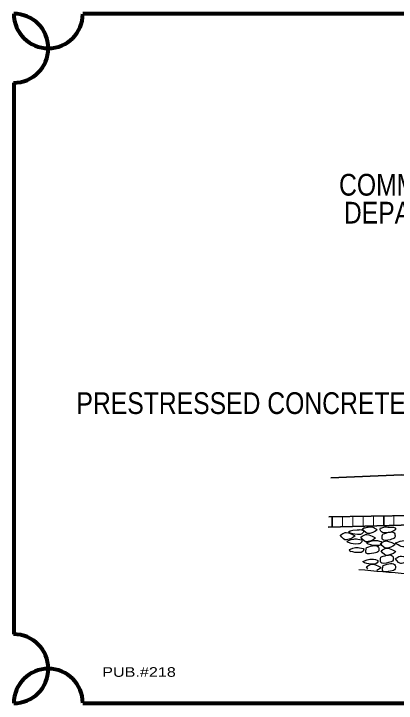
# Model space of a CAD drawing. Extents: x 763.8 to 797.8, y -170.3 to -127.3.
# Drawn here: x 764.76 to 775.84, y -147.27 to -127.27 of the extents above; entities that cross this region are included whole.
import ezdxf
from ezdxf.enums import TextEntityAlignment as Align

# ---------------------------------------------------------------- set-up
doc = ezdxf.new("R2010")
doc.units = 0
doc.header["$LTSCALE"] = 0.077
doc.layers.add('1', color=7, linetype='Continuous', lineweight=35)
doc.layers.add('63', color=7, linetype='Continuous', lineweight=13)

msp = doc.modelspace()

# ---------------------------------------------------------------- linework, layer by layer
at = {"layer": '1', "lineweight": 80}
for p, q in [((794.76075, -127.26542), (766.76075, -127.26542)), ((764.76075, -129.26542), (764.76075, -145.26542)), ((766.76075, -147.26542), (794.76075, -147.26542))]:
    msp.add_line(p, q, dxfattribs=at)
for centre, start, end in [((764.76073, -128.26542), 270, 90), ((765.76073, -127.26542), 180, 0), ((764.76073, -146.26542), 270, 90), ((765.76073, -147.26542), 0, 180)]:
    msp.add_arc(centre, 1, start, end, dxfattribs=at)
at = {"layer": '63', "lineweight": 35}
for p, q in [((773.89242, -141.85708), (776.85492, -141.81692)), ((773.98767, -141.85575), (773.98767, -142.1575)), ((775.48767, -141.83542), (775.48767, -142.112)), ((773.86917, -142.16108), (776.56758, -142.07925))]:
    msp.add_line(p, q, dxfattribs=at)
at = {"layer": '63'}
for p, q in [((774.28767, -141.85167), (774.28767, -142.14842)), ((774.58767, -141.84767), (774.58767, -142.13925)), ((774.88767, -141.84358), (774.88767, -142.13017)), ((775.18767, -141.8395), (775.18767, -142.12108)), ((775.77567, -141.8315), (775.77567, -142.10325))]:
    msp.add_line(p, q, dxfattribs=at)
at = {"layer": '63', "lineweight": 25}
msp.add_line((775.02017, -143.36542), (774.979, -143.31008), dxfattribs=at)
at = {"layer": '63', "lineweight": 35}
msp.add_lwpolyline([(773.95008, -140.723), (776.00742, -140.6415), (776.92408, -140.65583)], dxfattribs=at)
at = {"layer": '63', "lineweight": 25}
for points in [[(775.19208, -142.17617), (775.19975, -142.17883), (775.27542, -142.2165), (775.28433, -142.23358), (775.27275, -142.25175), (775.22142, -142.2865), (775.16758, -142.31133), (775.08317, -142.339), (775.04742, -142.34583), (775.021, -142.34617), (774.99975, -142.33983), (774.96142, -142.31675), (774.907, -142.26458), (774.86592, -142.20925)], [(774.87075, -142.20567), (774.90983, -142.179), (774.92233, -142.17142)], [(775.827, -142.18742), (775.82808, -142.20225), (775.82208, -142.224), (775.80567, -142.24308), (775.77725, -142.2625), (775.727, -142.28892), (775.66992, -142.31092), (775.645, -142.31725), (775.59483, -142.323), (775.55475, -142.32333), (775.49625, -142.3185), (775.447, -142.3085), (775.41967, -142.29508), (775.40125, -142.277), (775.38267, -142.23733), (775.38142, -142.20592), (775.38825, -142.18442), (775.39167, -142.17975)], [(774.22742, -142.38717), (774.2665, -142.3605), (774.29825, -142.34133), (774.32283, -142.32908), (774.36017, -142.31667), (774.37875, -142.31408), (774.39708, -142.3145), (774.45833, -142.32675), (774.55642, -142.36033), (774.63217, -142.39808), (774.641, -142.41517), (774.6295, -142.43333), (774.57808, -142.46808), (774.52425, -142.49283), (774.43983, -142.52058), (774.40408, -142.52742), (774.37767, -142.52775), (774.3565, -142.52142), (774.31817, -142.49833), (774.26367, -142.44617), (774.22258, -142.39083)], [(774.78142, -142.22808), (774.83767, -142.23833), (774.885, -142.25117), (774.90183, -142.26183), (774.907, -142.27525), (774.89867, -142.30408), (774.8815, -142.32675), (774.84517, -142.35608), (774.82492, -142.36592), (774.805, -142.37117), (774.72083, -142.37242), (774.64408, -142.36433), (774.58658, -142.35333), (774.51258, -142.32917), (774.48567, -142.31367), (774.46817, -142.296)], [(774.46817, -142.29117), (774.51325, -142.26958), (774.58883, -142.24458)], [(774.58325, -142.24708), (774.7105, -142.23442), (774.76775, -142.23442)], [(774.82225, -142.4455), (774.86142, -142.41892), (774.89308, -142.39975), (774.91767, -142.3875), (774.955, -142.375), (774.97358, -142.37242), (774.99192, -142.37283), (775.05325, -142.38517), (775.15125, -142.41875), (775.227, -142.45642), (775.23592, -142.4735), (775.22433, -142.49167), (775.173, -142.52642), (775.11908, -142.55117), (775.03467, -142.57892), (774.999, -142.58575), (774.97258, -142.58608), (774.95133, -142.57975), (774.913, -142.55667), (774.85858, -142.5045), (774.81742, -142.44917)], [(774.4185, -142.56667), (774.46367, -142.54508), (774.53917, -142.52), (774.61725, -142.50242), (774.64283, -142.49925), (774.69275, -142.4995), (774.73175, -142.5035), (774.78808, -142.51383), (774.83542, -142.52667), (774.85225, -142.53733), (774.85733, -142.55075), (774.84908, -142.5795), (774.83183, -142.60225), (774.7955, -142.6315), (774.77533, -142.64142), (774.75542, -142.64667), (774.67125, -142.64792), (774.59442, -142.63983), (774.537, -142.62883), (774.463, -142.60467), (774.436, -142.58917), (774.4185, -142.5715)], [(774.98892, -142.61275), (775.03408, -142.59117), (775.10958, -142.56608), (775.18767, -142.5485), (775.21325, -142.54533), (775.26317, -142.54558), (775.30217, -142.54958), (775.3585, -142.55992), (775.40583, -142.57275), (775.42267, -142.58342), (775.42775, -142.59675), (775.4195, -142.62558), (775.40225, -142.64833), (775.36592, -142.67758), (775.34575, -142.6875), (775.32583, -142.69275), (775.24167, -142.694), (775.16483, -142.68592), (775.10742, -142.67492), (775.03342, -142.65067), (775.00642, -142.63525), (774.98892, -142.61758)], [(775.39133, -142.63167), (775.43042, -142.605), (775.46217, -142.58583), (775.48675, -142.57358), (775.52408, -142.56117), (775.54267, -142.5585), (775.561, -142.55892), (775.62225, -142.57125), (775.72025, -142.60483), (775.79608, -142.64258), (775.80492, -142.65967), (775.79333, -142.67783), (775.742, -142.7125), (775.68817, -142.73733), (775.60375, -142.76508), (775.568, -142.77183), (775.54158, -142.77225), (775.52033, -142.76592), (775.482, -142.74275), (775.42758, -142.69067), (775.3865, -142.63533)], [(774.49142, -142.80608), (774.515, -142.79483), (774.59058, -142.76983), (774.66858, -142.75225), (774.69425, -142.749), (774.74408, -142.74933), (774.78317, -142.75333), (774.83942, -142.76358), (774.88675, -142.77642), (774.90358, -142.78708), (774.90875, -142.8005), (774.90042, -142.82933), (774.88325, -142.852), (774.84683, -142.88133), (774.82667, -142.89117), (774.80675, -142.89642), (774.72258, -142.89767), (774.64575, -142.88958), (774.58833, -142.87858), (774.53167, -142.86008)], [(775.41258, -142.84067), (775.45167, -142.814), (775.48342, -142.79492), (775.50792, -142.78258), (775.54533, -142.77017), (775.56383, -142.76758), (775.58225, -142.768), (775.6435, -142.78025), (775.7415, -142.81383), (775.81725, -142.85158), (775.82617, -142.86867), (775.81458, -142.88683), (775.76325, -142.92158), (775.70933, -142.94633), (775.62492, -142.97408), (775.58925, -142.98092), (775.56283, -142.98125), (775.54158, -142.97492), (775.50325, -142.95183), (775.44883, -142.89967), (775.40775, -142.84433)], [(774.49425, -142.81317), (774.4815, -142.82908), (774.526, -142.86408)], [(775.82392, -143.07008), (775.863, -143.0435), (775.89475, -143.02425), (775.91933, -143.012), (775.95667, -142.99958), (775.97525, -142.997), (775.99358, -142.99742), (776.05483, -143.00967), (776.15292, -143.04333), (776.22867, -143.081), (776.2375, -143.09808), (776.226, -143.11625), (776.17458, -143.151), (776.12075, -143.17575), (776.03633, -143.2035), (776.00058, -143.21033), (775.97417, -143.21067), (775.953, -143.20433), (775.91467, -143.18125), (775.86025, -143.12908), (775.81908, -143.07375)], [(774.87742, -143.153), (774.9225, -143.13142), (774.99808, -143.10642), (775.07608, -143.08883), (775.10175, -143.08567), (775.15158, -143.08592), (775.19058, -143.08992), (775.24692, -143.10025), (775.29425, -143.11308), (775.31108, -143.12367), (775.31625, -143.13708), (775.30792, -143.16592), (775.29075, -143.18867), (775.25433, -143.21792), (775.23417, -143.22783), (775.21425, -143.233), (775.13008, -143.23433), (775.05325, -143.22625), (774.99583, -143.21517), (774.92183, -143.191), (774.89483, -143.1755), (774.87742, -143.15792)], [(774.98383, -143.30642), (775.023, -143.27983), (775.05467, -143.26058), (775.07925, -143.24842), (775.11658, -143.23592), (775.13517, -143.23333), (775.1535, -143.23375), (775.21475, -143.246), (775.31283, -143.27958), (775.38858, -143.31733), (775.3975, -143.33442), (775.38592, -143.35258), (775.33458, -143.38733), (775.28067, -143.41208)]]:
    msp.add_lwpolyline(points, dxfattribs=at)
for points in [[(774.91408, -142.18033), (775.03492, -142.15483), (775.1685, -142.15483), (775.22575, -142.19625)], [(775.40383, -142.18983), (775.51833, -142.15167), (775.69008, -142.16125), (775.7855, -142.16442), (775.83633, -142.193)], [(775.45675, -142.35642), (775.80083, -142.35642), (775.80333, -142.45333), (775.66758, -142.52117), (775.44467, -142.51875), (775.45192, -142.36)], [(775.81725, -142.61717), (776.016, -142.55292), (776.23417, -142.57717), (776.15417, -142.69717), (775.81725, -142.622)], [(774.98958, -142.74758), (775.33375, -142.74758), (775.33617, -142.8445), (775.20042, -142.91242), (774.9775, -142.91), (774.98475, -142.75125)], [(775.40767, -143.02308), (775.75183, -143.02308), (775.75425, -143.12), (775.6185, -143.18792), (775.39558, -143.18542), (775.40283, -143.02675)], [(775.46958, -143.26892), (775.81367, -143.26892), (775.81608, -143.36583), (775.68042, -143.43367), (775.45742, -143.43125), (775.46467, -143.2725)], [(774.76333, -143.38383), (777.55358, -143.62433), (779.30917, -143.74517), (781.84083, -143.9105), (783.571, -144.07592)]]:
    msp.add_spline(points, degree=3, dxfattribs=at)

# ---------------------------------------------------------------- texts
at = {"layer": '1'}
for s, height, width, p in [('COMMONWEALTH OF PENNSYLVANIA', 0.63, 0.85, (780.79229, -132.54008)), ('DEPARTMENT OF TRANSPORTATION', 0.63, 0.85, (780.79229, -133.35008)), ('PRESTRESSED CONCRETE,  REINFORCED CONCRETE AND STEEL STRUCTURES', 0.63, 0.85, (780.76067, -138.87558)), ('PUB.#218', 0.28, 1.25, (768.39058, -146.5))]:
    msp.add_text(s, height=height, dxfattribs=dict(at, width=width)).set_placement(p, align=Align.CENTER)

doc.saveas('drawing.dxf')
